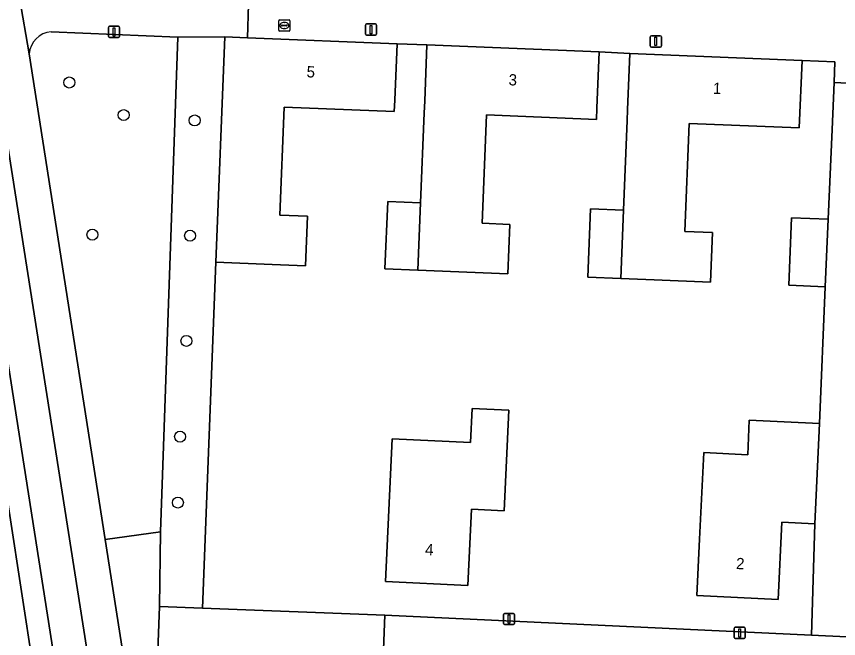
# Model space of a CAD drawing. Extents: x 160786 to 161429, y 386828 to 387485.
# Drawn here: x 160842.3 to 160915.3, y 387159.5 to 387214.7 of the extents above; entities that cross this region are included whole.
import ezdxf

# ---------------------------------------------------------------- set-up
doc = ezdxf.new("R2010")
doc.units = 0
for name, color, linetype in [('IMGEO_Berm_groen', 7, 'Continuous'), ('IMGEO_Boom', 7, 'Continuous'), ('IMGEO_Brandkraan', 7, 'Continuous'), ('IMGEO_Erf', 7, 'Continuous'), ('IMGEO_Fietspad_gesloten', 7, 'Continuous'), ('IMGEO_Groenvoorziening', 7, 'Continuous'), ('IMGEO_Lichtmast', 7, 'Continuous'), ('IMGEO_Muur', 7, 'Continuous'), ('IMGEO_Pand', 7, 'Continuous'), ('IMGEO_Pand_nummerreeks', 7, 'Continuous'), ('IMGEO_Rijbaan_lokaal_gesloten', 7, 'Continuous'), ('IMGEO_Rijbaan_lokaal_open', 7, 'Continuous'), ('IMGEO_Voetpad_open', 7, 'Continuous')]:
    doc.layers.add(name, color=color, linetype=linetype)

msp = doc.modelspace()

# ---------------------------------------------------------------- linework, layer by layer
at = {"layer": 'IMGEO_Berm_groen'}
msp.add_lwpolyline([(160842.596, 387177.288), (160836.374, 387216.975), (160833.16, 387237.408), (160832.411, 387248.937), (160829.437, 387248.454), (160829.724, 387246.655), (160831.427, 387235.974), (160834.472, 387216.74), (160837.463, 387197.457), (160840.657, 387177.21), (160843.786, 387156.959), (160846.832, 387137.716), (160850.314, 387115.477), (160850.801, 387112.345), (160852.723, 387112.646), (160852.187, 387116.071)], close=True, dxfattribs=at)
at = {"layer": 'IMGEO_Boom'}
for centre in [(160846.992, 387208.88), (160851.817, 387205.988), (160858.126, 387205.51), (160849.043, 387195.369), (160857.713, 387195.286), (160857.388, 387185.951), (160856.826, 387177.451), (160856.63, 387171.6)]:
    msp.add_circle(centre, 0.489, dxfattribs=at)
at = {"layer": 'IMGEO_Brandkraan'}
for p, q in [((160865.581, 387213.511), (160865.581, 387214.363)), ((160865.656, 387214.437), (160866.508, 387214.437)), ((160865.84, 387213.931), (160865.84, 387213.943)), ((160866.278, 387213.894), (160865.88, 387213.894)), ((160865.883, 387213.98), (160866.281, 387213.98)), ((160866.069, 387214.217), (160866.094, 387214.217)), ((160866.324, 387213.943), (160866.324, 387213.931)), ((160866.582, 387214.363), (160866.582, 387213.511)), ((160866.508, 387213.437), (160865.656, 387213.437)), ((160866.092, 387213.657), (160866.067, 387213.657))]:
    msp.add_line(p, q, dxfattribs=at)
for points in [[(160865.581, 387213.511), (160865.581, 387214.363)], [(160865.656, 387214.437), (160866.508, 387214.437)], [(160866.582, 387214.363), (160866.582, 387213.511)], [(160866.508, 387213.437), (160865.656, 387213.437)]]:
    msp.add_lwpolyline(points, dxfattribs=at)
for centre, radius, start, end in [((160865.658, 387214.361), 0.0765, 91.55205, 178.44795), ((160865.658, 387214.361), 0.0765, 91.55205, 178.44795), ((160865.88, 387213.94), 0.0403, 85.87752, 175.75265), ((160865.877, 387213.93), 0.0366, 178.93798, 274.71019), ((160866.281, 387213.937), 0.043, 264.86636, 352.45326), ((160866.285, 387213.942), 0.0386, 1.73085, 96.63898), ((160866.506, 387214.361), 0.0765, 1.55205, 88.44795), ((160866.506, 387214.361), 0.0765, 1.55205, 88.44795), ((160865.658, 387213.513), 0.0765, 181.55205, 268.44795), ((160865.658, 387213.513), 0.0765, 181.55205, 268.44795), ((160866.506, 387213.513), 0.0765, 271.55205, 358.44795), ((160866.506, 387213.513), 0.0765, 271.55205, 358.44795)]:
    msp.add_arc(centre, radius, start, end, dxfattribs=at)
for centre, major_axis, ratio, start_param, end_param in [((160866.068, 387213.937), (-0.387, 0.002), 0.722429, 4.712389, 7.853982), ((160866.093, 387213.937), (-0.39, 0.002), 0.717154, 1.570796, 4.712389)]:
    msp.add_ellipse(centre, major_axis=major_axis, ratio=ratio, start_param=start_param, end_param=end_param, dxfattribs=at)
at = {"layer": 'IMGEO_Erf'}
for points in [[(160914.106, 387190.757), (160910.869, 387190.887), (160911.111, 387196.884), (160914.348, 387196.743), (160914.724, 387204.715), (160914.892, 387208.871), (160914.967, 387210.721), (160912.045, 387210.839), (160911.802, 387204.856), (160902.019, 387205.253), (160901.631, 387195.663), (160904.091, 387195.564), (160903.912, 387191.165), (160898.917, 387191.368), (160895.955, 387191.488), (160893.011, 387191.607), (160893.256, 387197.655), (160896.2, 387197.536), (160896.523, 387205.494), (160896.562, 387206.463), (160896.765, 387211.458), (160894.025, 387211.588), (160893.823, 387206.593), (160893.783, 387205.605), (160884.035, 387206.001), (160883.646, 387196.386), (160886.106, 387196.287), (160885.927, 387191.888), (160877.934, 387192.213), (160875.016, 387192.331), (160875.259, 387198.326), (160878.177, 387198.208), (160878.501, 387206.194), (160878.542, 387207.212), (160878.744, 387212.207), (160876.089, 387212.298), (160875.887, 387207.303), (160875.846, 387206.302), (160866.068, 387206.699), (160865.68, 387197.108), (160868.14, 387197.009), (160867.961, 387192.611), (160864.993, 387192.731), (160859.997, 387192.933), (160858.804, 387162.228), (160874.993, 387161.62), (160912.884, 387159.831), (160913.174, 387169.721), (160910.252, 387169.859), (160909.93, 387163.006), (160902.716, 387163.345), (160902.951, 387168.34), (160903.312, 387176.031), (160907.216, 387175.847), (160907.361, 387178.927), (160910.442, 387178.781), (160913.593, 387178.632)], [(160885.588, 387170.881), (160882.688, 387171.017), (160882.369, 387164.24), (160875.065, 387164.584), (160875.661, 387177.27), (160882.613, 387176.943), (160882.755, 387179.963), (160886.008, 387179.81)]]:
    msp.add_lwpolyline(points, close=True, dxfattribs=at)
at = {"layer": 'IMGEO_Fietspad_gesloten'}
for points in [[(160831.123, 387260.671), (160832.003, 387255.207), (160832.253, 387251.354), (160832.411, 387248.937), (160833.16, 387237.408), (160836.374, 387216.975), (160842.596, 387177.288), (160852.187, 387116.071), (160852.723, 387112.646), (160853.062, 387110.484), (160861.916, 387053.966), (160866.488, 387024.997)], [(160895.192, 386882.357), (160892.332, 386890.984), (160890.69, 386896.733), (160890.27, 386898.714), (160890.17, 386899.184), (160874.389, 386993.578), (160868.406, 387032.171), (160836.614, 387234.349), (160835.892, 387241.342), (160835.079, 387254.335)]]:
    msp.add_lwpolyline(points, dxfattribs=at)
at = {"layer": 'IMGEO_Groenvoorziening'}
msp.add_lwpolyline([(160843.436, 387211.425), (160850.173, 387168.324), (160855.085, 387169.007), (160856.628, 387212.906), (160845.381, 387213.384)], dxfattribs=at)
for points in [[(160855.085, 387169.007), (160855.009, 387162.37), (160858.804, 387162.228), (160859.997, 387192.933), (160860.807, 387212.918), (160856.628, 387212.906)], [(160853.962, 387144.085), (160854.274, 387144.071), (160854.419, 387147.359), (160854.714, 387154.505), (160855.009, 387162.37), (160855.085, 387169.007), (160850.173, 387168.324)]]:
    msp.add_lwpolyline(points, close=True, dxfattribs=at)
msp.add_arc((160845.554, 387211.268), 2.123, 94.66067, 175.75027, dxfattribs=at)
at = {"layer": 'IMGEO_Lichtmast'}
for p, q in [((160850.569, 387213.867), (160851.359, 387213.867)), ((160851.359, 387213.867), (160850.569, 387213.867)), ((160873.279, 387213.174), (160873.279, 387213.974)), ((160873.279, 387213.974), (160873.279, 387213.174)), ((160873.379, 387214.074), (160874.169, 387214.074)), ((160874.169, 387214.074), (160873.379, 387214.074)), ((160874.269, 387213.974), (160874.269, 387213.174)), ((160874.269, 387213.174), (160874.269, 387213.974)), ((160850.469, 387212.967), (160850.469, 387213.767)), ((160850.469, 387213.767), (160850.469, 387212.967)), ((160851.459, 387213.767), (160851.459, 387212.967)), ((160851.459, 387212.967), (160851.459, 387213.767)), ((160851.359, 387212.867), (160850.569, 387212.867)), ((160850.569, 387212.867), (160851.359, 387212.867)), ((160874.169, 387213.074), (160873.379, 387213.074)), ((160873.379, 387213.074), (160874.169, 387213.074)), ((160898.566, 387212.127), (160898.566, 387212.927)), ((160898.566, 387212.927), (160898.566, 387212.127)), ((160898.666, 387213.027), (160899.456, 387213.027)), ((160899.456, 387213.027), (160898.666, 387213.027)), ((160899.556, 387212.927), (160899.556, 387212.127)), ((160899.556, 387212.127), (160899.556, 387212.927)), ((160899.456, 387212.027), (160898.666, 387212.027)), ((160898.666, 387212.027), (160899.456, 387212.027)), ((160885.533, 387160.871), (160885.533, 387161.671)), ((160885.533, 387161.671), (160885.533, 387160.871)), ((160885.633, 387161.771), (160886.423, 387161.771)), ((160886.423, 387161.771), (160885.633, 387161.771)), ((160886.523, 387161.671), (160886.523, 387160.871)), ((160886.523, 387160.871), (160886.523, 387161.671)), ((160886.423, 387160.771), (160885.633, 387160.771)), ((160885.633, 387160.771), (160886.423, 387160.771)), ((160906.003, 387159.634), (160906.003, 387160.434)), ((160906.003, 387160.434), (160906.003, 387159.634)), ((160906.103, 387160.534), (160906.893, 387160.534)), ((160906.893, 387160.534), (160906.103, 387160.534)), ((160906.993, 387160.434), (160906.993, 387159.634)), ((160906.993, 387159.634), (160906.993, 387160.434)), ((160906.893, 387159.534), (160906.103, 387159.534)), ((160906.103, 387159.534), (160906.893, 387159.534))]:
    msp.add_line(p, q, dxfattribs=at)
for points in [[(160873.699, 387213.949), (160873.849, 387213.949), (160873.849, 387213.199), (160873.699, 387213.199), (160873.699, 387213.949)], [(160850.889, 387213.742), (160851.039, 387213.742), (160851.039, 387212.992), (160850.889, 387212.992), (160850.889, 387213.742)], [(160898.986, 387212.902), (160899.136, 387212.902), (160899.136, 387212.152), (160898.986, 387212.152), (160898.986, 387212.902)], [(160885.953, 387161.646), (160886.103, 387161.646), (160886.103, 387160.896), (160885.953, 387160.896), (160885.953, 387161.646)], [(160906.423, 387160.409), (160906.573, 387160.409), (160906.573, 387159.659), (160906.423, 387159.659), (160906.423, 387160.409)]]:
    msp.add_lwpolyline(points, dxfattribs=at)
for centre, start, end in [((160850.569, 387213.767), 90, 180), ((160850.569, 387213.767), 90, 180), ((160851.359, 387213.767), 0, 90), ((160851.359, 387213.767), 360, 90), ((160873.379, 387213.974), 90, 180), ((160873.379, 387213.974), 90, 180), ((160874.169, 387213.974), 0, 90), ((160874.169, 387213.974), 360, 90), ((160873.379, 387213.174), 180, 270), ((160873.379, 387213.174), 180, 270), ((160874.169, 387213.174), 270, 0), ((160874.169, 387213.174), 270, 0), ((160850.569, 387212.967), 180, 270), ((160850.569, 387212.967), 180, 270), ((160851.359, 387212.967), 270, 0), ((160851.359, 387212.967), 270, 0), ((160898.666, 387212.927), 90, 180), ((160898.666, 387212.927), 90, 180), ((160899.456, 387212.927), 0, 90), ((160899.456, 387212.927), 360, 90), ((160898.666, 387212.127), 180, 270), ((160898.666, 387212.127), 180, 270), ((160899.456, 387212.127), 270, 0), ((160899.456, 387212.127), 270, 0), ((160885.633, 387161.671), 90, 180), ((160885.633, 387161.671), 90, 180), ((160886.423, 387161.671), 0, 90), ((160886.423, 387161.671), 360, 90), ((160885.633, 387160.871), 180, 270), ((160885.633, 387160.871), 180, 270), ((160886.423, 387160.871), 270, 0), ((160886.423, 387160.871), 270, 0), ((160906.103, 387160.434), 90, 180), ((160906.103, 387160.434), 90, 180), ((160906.893, 387160.434), 0, 90), ((160906.893, 387160.434), 360, 90), ((160906.103, 387159.634), 180, 270), ((160906.103, 387159.634), 180, 270), ((160906.893, 387159.634), 270, 0), ((160906.893, 387159.634), 270, 0)]:
    msp.add_arc(centre, 0.1, start, end, dxfattribs=at)
at = {"layer": 'IMGEO_Muur'}
msp.add_lwpolyline([(160914.724, 387204.715), (160914.892, 387208.871)], dxfattribs=at)
at = {"layer": 'IMGEO_Pand'}
for points in [[(160860.807, 387212.918), (160859.997, 387192.933), (160864.993, 387192.731), (160867.961, 387192.611), (160868.14, 387197.009), (160865.68, 387197.108), (160866.068, 387206.699), (160875.846, 387206.302), (160875.887, 387207.303), (160876.089, 387212.298), (160862.811, 387212.837)], [(160885.927, 387191.888), (160886.106, 387196.287), (160883.646, 387196.386), (160884.035, 387206.001), (160893.783, 387205.605), (160893.823, 387206.593), (160894.025, 387211.588), (160878.744, 387212.207), (160878.542, 387207.212), (160878.501, 387206.194), (160878.177, 387198.208), (160877.934, 387192.213)], [(160898.917, 387191.368), (160903.912, 387191.165), (160904.091, 387195.564), (160901.631, 387195.663), (160902.019, 387205.253), (160911.802, 387204.856), (160912.045, 387210.839), (160896.765, 387211.458), (160896.562, 387206.463), (160896.523, 387205.494), (160896.2, 387197.536), (160895.955, 387191.488)], [(160877.934, 387192.213), (160878.177, 387198.208), (160875.259, 387198.326), (160875.016, 387192.331)], [(160895.955, 387191.488), (160896.2, 387197.536), (160893.256, 387197.655), (160893.011, 387191.607)], [(160914.348, 387196.743), (160911.111, 387196.884), (160910.869, 387190.887), (160914.106, 387190.757)], [(160882.688, 387171.017), (160885.588, 387170.881), (160886.008, 387179.81), (160882.755, 387179.963), (160882.613, 387176.943), (160875.661, 387177.27), (160875.065, 387164.584), (160882.369, 387164.24)], [(160913.593, 387178.632), (160910.442, 387178.781), (160907.361, 387178.927), (160907.216, 387175.847), (160903.312, 387176.031), (160902.951, 387168.34), (160902.716, 387163.345), (160909.93, 387163.006), (160910.252, 387169.859), (160913.174, 387169.721)], [(160874.296, 387143.28), (160874.993, 387161.62), (160858.804, 387162.228), (160855.009, 387162.37), (160854.714, 387154.505), (160859.112, 387154.34), (160859.202, 387156.732), (160868.791, 387156.372), (160868.308, 387143.505)]]:
    msp.add_lwpolyline(points, close=True, dxfattribs=at)
at = {"layer": 'IMGEO_Rijbaan_lokaal_gesloten'}
msp.add_lwpolyline([(160853.309, 387096.223), (160851.138, 387110.182), (160850.801, 387112.345), (160850.314, 387115.477), (160846.832, 387137.716), (160843.786, 387156.959), (160840.657, 387177.21), (160837.463, 387197.457), (160834.472, 387216.74), (160831.427, 387235.974), (160829.724, 387246.655), (160823.831, 387245.653), (160824.417, 387241.911), (160824.689, 387240.174), (160824.752, 387239.782), (160835.704, 387169.823), (160841.78, 387131.053)], dxfattribs=at)
at = {"layer": 'IMGEO_Rijbaan_lokaal_open'}
for points in [[(160904.338, 387227.48), (160904.594, 387232.11), (160863.581, 387234.194), (160862.892, 387215.805), (160862.811, 387212.837), (160876.089, 387212.298), (160878.744, 387212.207), (160894.025, 387211.588), (160896.765, 387211.458), (160912.045, 387210.839), (160914.967, 387210.721), (160914.892, 387208.871), (160920.768, 387208.584)], [(160916.006, 387159.69), (160912.884, 387159.831), (160874.993, 387161.62), (160874.296, 387143.28), (160874.183, 387140.315), (160887.456, 387139.767), (160890.025, 387139.644), (160905.377, 387139.03), (160908.088, 387138.951), (160923.499, 387138.336)]]:
    msp.add_lwpolyline(points, dxfattribs=at)
at = {"layer": 'IMGEO_Voetpad_open'}
for points in [[(160835.079, 387254.335), (160835.892, 387241.342), (160836.614, 387234.349), (160868.406, 387032.171), (160874.389, 386993.578), (160890.17, 386899.184), (160890.27, 386898.714), (160890.69, 386896.733), (160892.332, 386890.984), (160895.192, 386882.357)], [(160843.436, 387211.425), (160842.556, 387216.426), (160840.358, 387230.871)], [(160862.892, 387215.805), (160856.962, 387216.027), (160848.958, 387216.231), (160843.074, 387216.41), (160842.556, 387216.426), (160843.436, 387211.425)], [(160845.381, 387213.384), (160856.628, 387212.906), (160860.807, 387212.918), (160862.811, 387212.837), (160862.892, 387215.805)], [(160894.345, 386893.433), (160893.879, 386895.647), (160893.47, 386897.821), (160893.178, 386900.21), (160892.82, 386902.33), (160892.761, 386902.682), (160889.526, 386921.865), (160888.698, 386926.241), (160885.382, 386946.825), (160883.927, 386955.541), (160877.451, 386994.335), (160876.715, 386998.837), (160872.018, 387028.888), (160866.195, 387066.141), (160865.276, 387071.519), (160860.793, 387100.291), (160854.76, 387139.009), (160853.962, 387144.085), (160850.173, 387168.324), (160843.436, 387211.425)]]:
    msp.add_lwpolyline(points, dxfattribs=at)
msp.add_lwpolyline([(160914.724, 387204.715), (160914.348, 387196.743), (160914.106, 387190.757), (160913.593, 387178.632), (160913.174, 387169.721), (160912.884, 387159.831), (160916.006, 387159.69), (160917.765, 387202.667), (160917.511, 387202.678), (160917.767, 387208.711), (160920.768, 387208.584), (160914.892, 387208.871)], close=True, dxfattribs=at)
msp.add_arc((160845.554, 387211.268), 2.123, 94.66067, 175.75027, dxfattribs=at)

# ---------------------------------------------------------------- texts
at = {"layer": 'IMGEO_Pand_nummerreeks'}
for s, rotation, p in [('5', 357.67675, (160868.04, 387209.342)), ('3', 357.68034, (160885.977, 387208.632)), ('1', 357.68019, (160904.112, 387207.878)), ('4', 357.30351, (160878.56, 387166.942)), ('2', 357.3071, (160906.164, 387165.705))]:
    msp.add_text(s, height=1, rotation=rotation, dxfattribs=at).set_placement(p)

doc.saveas('drawing.dxf')
